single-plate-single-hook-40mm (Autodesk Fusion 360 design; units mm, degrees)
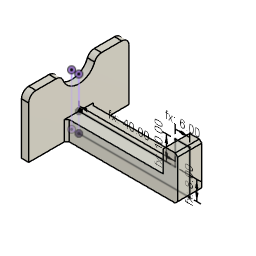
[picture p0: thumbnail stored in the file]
parameter "HangerDepth" = 40
parameter "TabHeight" = 10
parameter "TabWidth" = 10
parameter "Thickness" = 8
parameter "TabDepth" = 6
base_feature "Base Feature" bodies "Single Plate Blank", "Single Plate Hook 42mm"
fillet "Fillet1" radius 3
sketch "Sketch1" plane through (0, 0, 0) normal (0, 1, 0) x axis (1, 0, 0)
  line L1 (96.15, 180.7602) -> (99.15, 180.7602)
  line L2 (96.15, 202.1244) -> (96.15, 180.7602)
  line L3 (99.15, 202.1244) -> (96.15, 202.1244)
  line L4 (99.15, 180.7602) -> (99.15, 202.1244)
  line L5 (145.15, 202.1244) -> (99.15, 202.1244)
  line L6 (145.15, 184.1244) -> (145.15, 202.1244)
  line L7 (139.15, 184.1244) -> (145.15, 184.1244)
  line L8 (139.15, 194.1244) -> (139.15, 184.1244)
  line L9 (99.15, 194.1244) -> (139.15, 194.1244)
  point P5 (99.15, 202.1244)
  point P6 (99.15, 202.1244)
  point P11 (99.15, 194.1244)
  point P8 (145.15, 184.1244)
  point P9 (139.15, 184.1244)
  point P10 (139.15, 194.1244)
  coincident P5 P6
  perpendicular L4 L5
  perpendicular L5 L6
  perpendicular L6 L7
  perpendicular L7 L8
  coincident L4 P11
  perpendicular L4 L9
  dimension "d5" distance P8 P9 = 6 (= "TabDepth")
  dimension "d6" distance P9 P10 = 10 (= "TabHeight")
  dimension "d18" distance L5 L9 = 8 (= "Thickness")
  dimension "d20" distance P10 P11 = 40 (= "HangerDepth")
extrude "Extrude1" add sketch "Sketch1" profile of L4 L5 L6 L7 L8 L9 distance 5 (= "TabWidth / 2")
chamfer "Chamfer1" distance 1
move_face "MoveFace1"
move_face "MoveFace2"
named bodies: "Single Plate Blank", "Single Plate Hook 42mm"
